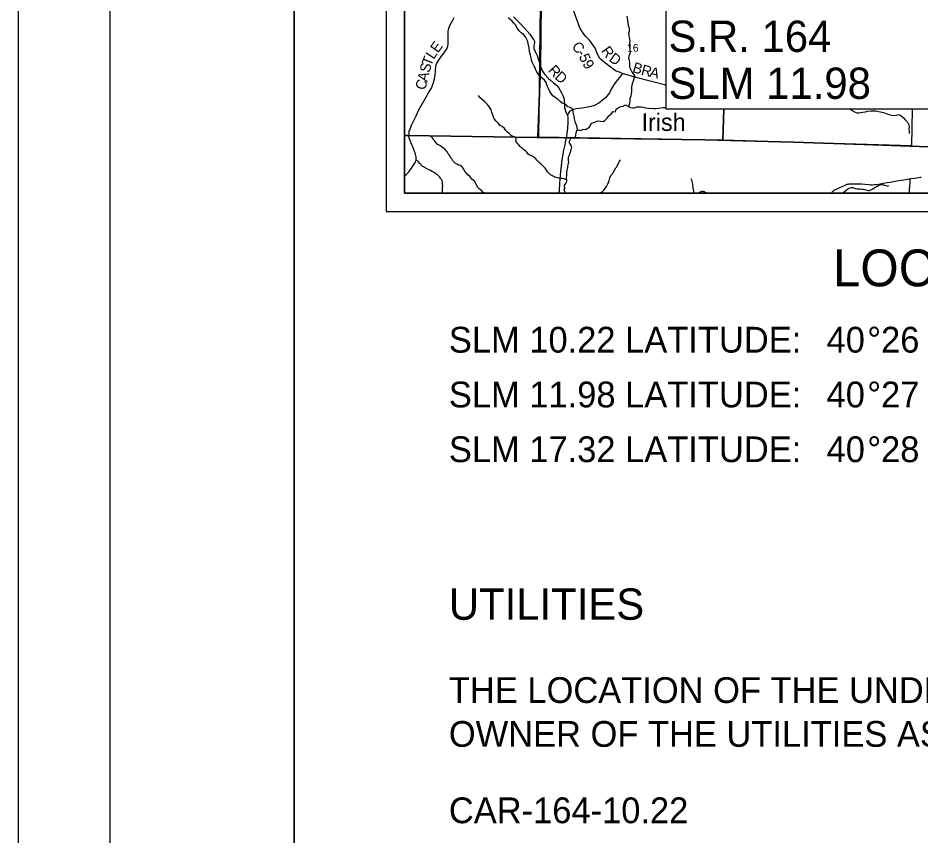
# Model space of a CAD drawing. Extents: x -20.5 to 34, y -66 to 23.9.
# Drawn here: x 0 to 4.905, y 10.61 to 15.05 of the extents above; entities that cross this region are included whole.
import ezdxf

# ---------------------------------------------------------------- set-up
doc = ezdxf.new("R2010")
doc.units = 0
for name, color, linetype in [('Default', 7, 'Continuous'), ('GM_X_County_Road_Text', 7, 'Continuous'), ('GM_X_County_Text', 7, 'Continuous'), ('GM_X_Minor_Lake', 7, 'Continuous'), ('GM_X_Minor_River_Text', 7, 'Continuous'), ('GM_X_Section_Text', 7, 'Continuous'), ('GM_X_State_Route', 7, 'Continuous'), ('GM_X_Township_Road_Text', 7, 'Continuous'), ('GM_X_Township_Text', 7, 'Continuous'), ('SH_Border', 7, 'Continuous'), ('SH_Cut_Line', 7, 'Continuous'), ('SH_Data', 7, 'Continuous'), ('SH_Text', 7, 'Continuous')]:
    doc.layers.add(name, color=color, linetype=linetype)

msp = doc.modelspace()

# ---------------------------------------------------------------- linework, layer by layer
at = {"layer": 'Default'}
for points in [[(2.1, 20.9), (8.9, 20.9), (8.9, 14.1), (2.1, 14.1)], [(2.1, 14.4131), (2.1, 14.1), (7.0561, 14.1), (7.0584, 14.2237), (7.0621, 14.3264), (6.9781, 14.3273), (6.3081, 14.3344), (6.1363, 14.3365), (5.5684, 14.3427), (5.292, 14.3455), (5.219, 14.3463), (4.9964, 14.3486), (4.5952, 14.364), (4.213, 14.3756), (3.7322, 14.3888), (2.969, 14.3992), (2.823, 14.4012), (2.8202, 14.4012), (2.1154, 14.4129)]]:
    msp.add_lwpolyline(points, close=True, dxfattribs=at)
for points in [[(2.88, 18.0245), (2.8801, 18.0269), (2.8826, 18.5075), (2.8861, 18.9025), (2.8866, 19.0123), (2.1138, 19.0238), (2.1, 19.024), (2.1, 14.4131), (2.1154, 14.4129), (2.8202, 14.4012), (2.823, 14.4012), (2.8374, 14.7884), (2.8447, 15.4785), (2.8665, 16.4374), (2.8739, 17.2409)], [(2.8447, 15.4785), (2.8374, 14.7884), (2.823, 14.4012), (2.969, 14.3992), (3.7322, 14.3888), (4.213, 14.3756), (4.5952, 14.364), (4.9964, 14.3486), (5.219, 14.3463), (5.292, 14.3455), (5.5684, 14.3427), (6.1363, 14.3365), (6.3081, 14.3344), (6.9781, 14.3273), (7.0621, 14.3264), (7.1219, 14.3257), (7.8132, 14.3208), (8.0565, 14.3169), (8.0585, 14.4588), (8.0589, 14.5033), (8.0605, 14.6038), (8.0662, 14.9881), (8.0784, 15.8902)]]:
    msp.add_lwpolyline(points, dxfattribs=at)
at = {"layer": 'GM_X_County_Text'}
for points in [[(2.6908, 15.0567), (2.7066, 15.0429), (2.7294, 15.0198), (2.752, 14.9952), (2.7804, 14.962), (2.7942, 14.9419), (2.8012, 14.9328), (2.8052, 14.9254), (2.8061, 14.9174), (2.8045, 14.9069), (2.802, 14.8968), (2.8022, 14.8851), (2.8083, 14.8696), (2.8197, 14.8462), (2.8257, 14.8294), (2.8314, 14.8119), (2.8347, 14.7983)], [(2.8347, 14.7983), (2.8354, 14.7954), (2.8376, 14.7878), (2.8485, 14.7625), (2.86, 14.7456), (2.8812, 14.7225), (2.892, 14.7128), (2.9084, 14.6989), (2.9251, 14.6855), (2.9359, 14.6724), (2.9499, 14.6479), (2.9614, 14.6253), (2.9663, 14.6092), (2.9676, 14.5727), (2.9691, 14.5622), (2.972, 14.5522), (2.9765, 14.5405), (2.98, 14.5326), (2.9851, 14.5205)], [(2.3064, 14.1), (2.3063, 14.1063), (2.3063, 14.1124), (2.3066, 14.1339), (2.3067, 14.1398), (2.3066, 14.1481), (2.3064, 14.1532), (2.3059, 14.1574), (2.3052, 14.1612), (2.3045, 14.1641), (2.3037, 14.1668), (2.3027, 14.1694), (2.3014, 14.1721), (2.2993, 14.1758), (2.2971, 14.1791), (2.2951, 14.1818), (2.2904, 14.187), (2.2869, 14.1904), (2.2797, 14.1967), (2.2741, 14.2012), (2.2671, 14.2067), (2.2619, 14.2106), (2.2574, 14.2135), (2.2504, 14.2177), (2.2398, 14.223), (2.2281, 14.2286), (2.2158, 14.2348), (2.2078, 14.239), (2.2023, 14.242), (2.198, 14.245), (2.1955, 14.2468), (2.1928, 14.2491), (2.1901, 14.2516), (2.1874, 14.2543), (2.1819, 14.2607), (2.1739, 14.2709), (2.1719, 14.2731), (2.1693, 14.2755), (2.1669, 14.2772), (2.1645, 14.2786), (2.1624, 14.2797)], [(4.4182, 14.1), (4.4191, 14.1011), (4.4225, 14.1052), (4.4248, 14.1079), (4.4273, 14.1103), (4.4302, 14.1128), (4.4336, 14.1155), (4.4366, 14.1174), (4.4393, 14.119), (4.4456, 14.122), (4.4601, 14.1286), (4.4836, 14.1396), (4.4924, 14.1438), (4.4966, 14.1455), (4.5028, 14.1477), (4.509, 14.1492), (4.5143, 14.1501), (4.5199, 14.1507), (4.5249, 14.1508), (4.5343, 14.1507), (4.5558, 14.1506), (4.5634, 14.1505), (4.5718, 14.1502), (4.5786, 14.1499), (4.5841, 14.1496), (4.6, 14.1481), (4.6229, 14.1459), (4.6315, 14.1454), (4.6415, 14.1456), (4.6525, 14.146), (4.664, 14.1469), (4.6742, 14.1481), (4.7013, 14.153), (4.7214, 14.1571), (4.737, 14.16), (4.7555, 14.1635), (4.7739, 14.1664), (4.797, 14.1696), (4.812, 14.1719), (4.8208, 14.1735), (4.831, 14.1753), (4.8416, 14.1772), (4.8471, 14.1782), (4.8517, 14.179), (4.8673, 14.1813), (4.883, 14.1833), (4.8916, 14.1845), (4.8998, 14.1859), (4.906, 14.1867)], [(4.8419, 14.1), (4.8427, 14.1188), (4.8434, 14.1267), (4.8439, 14.132), (4.8449, 14.1428), (4.8458, 14.153), (4.8467, 14.1695), (4.8471, 14.1782)], [(3.7009, 14.1), (3.7012, 14.1007), (3.7022, 14.1029), (3.7033, 14.1044), (3.7052, 14.1061), (3.7077, 14.1076), (3.7104, 14.1087), (3.7125, 14.1094), (3.7145, 14.1098), (3.717, 14.1099), (3.7193, 14.1097), (3.7234, 14.1088), (3.7265, 14.1079), (3.7296, 14.1066), (3.7397, 14.1021), (3.7452, 14.1)]]:
    msp.add_lwpolyline(points, dxfattribs=at)
at = {"layer": 'GM_X_Minor_Lake'}
for points in [[(3.8345, 14.5564), (3.829, 14.3877), (2.8293, 14.4033), (2.8417, 15.4083), (3.8622, 15.401), (3.8602, 15.34)], [(4.8577, 14.5564), (4.8536, 14.3565), (3.829, 14.3877), (3.8345, 14.5564)]]:
    msp.add_lwpolyline(points, dxfattribs=at)
at = {"layer": 'GM_X_Minor_River_Text'}
for points in [[(3.3171, 14.5698), (3.3235, 14.5862), (3.3244, 14.6014), (3.3261, 14.6147), (3.33, 14.628), (3.3317, 14.6387), (3.3338, 14.6512), (3.3339, 14.6649), (3.3341, 14.6744), (3.3366, 14.687), (3.3402, 14.6995), (3.343, 14.7095), (3.3462, 14.7205), (3.3505, 14.7358), (3.3454, 14.7463), (3.3358, 14.7564), (3.3315, 14.7677), (3.3225, 14.7812), (3.3227, 14.793), (3.3232, 14.8074), (3.3207, 14.8214), (3.3183, 14.8312), (3.3199, 14.8453), (3.3258, 14.8575), (3.3264, 14.867), (3.3251, 14.8788), (3.3226, 14.8928), (3.3224, 14.9038), (3.323, 14.9148), (3.325, 14.927), (3.3213, 14.9444), (3.3189, 14.9557), (3.3183, 14.9675), (3.3215, 14.9789), (3.3217, 14.9933), (3.3169, 15.0084), (3.3136, 15.0243), (3.3122, 15.0364), (3.3105, 15.0489), (3.3092, 15.0614)], [(3.0393, 14.4413), (3.0376, 14.4573), (3.034, 14.4679), (3.0285, 14.481), (3.0225, 14.5037), (3.0207, 14.5185), (3.0182, 14.5321), (3.0154, 14.5438), (3.0094, 14.5585), (2.9964, 14.5659), (2.9866, 14.5691), (2.9773, 14.5788), (2.9662, 14.5843), (2.9567, 14.5883), (2.9448, 14.598), (2.9329, 14.6099), (2.918, 14.6184), (2.9049, 14.6281), (2.8953, 14.6408), (2.8887, 14.6517), (2.8812, 14.6671), (2.8761, 14.678), (2.8718, 14.6882), (2.8682, 14.7007), (2.8604, 14.7138), (2.8473, 14.7246), (2.8362, 14.7332), (2.8277, 14.744), (2.8199, 14.7549), (2.8125, 14.7677), (2.8085, 14.7794), (2.8038, 14.7891), (2.7984, 14.7993), (2.7933, 14.8113), (2.79, 14.8219), (2.7872, 14.834), (2.7832, 14.8487), (2.7807, 14.8608), (2.779, 14.8707), (2.7757, 14.8854), (2.774, 14.8972), (2.7719, 14.9096), (2.7691, 14.9233), (2.7616, 14.9372), (2.7569, 14.9481), (2.745, 14.9612), (2.7327, 14.9693), (2.7223, 14.9809), (2.713, 14.9933), (2.7028, 15.0136), (2.6925, 15.0225), (2.6836, 15.0334), (2.672, 15.0442), (2.6617, 15.0523)], [(2.7008, 14.403), (2.6891, 14.4074), (2.6796, 14.4126), (2.6696, 14.4215), (2.6588, 14.4301), (2.6492, 14.4405), (2.6418, 14.4503), (2.6295, 14.4618), (2.6196, 14.4677), (2.608, 14.4797), (2.5976, 14.4905), (2.5872, 14.5036), (2.5805, 14.5171), (2.5766, 14.5277), (2.5738, 14.5379), (2.5701, 14.5515), (2.5647, 14.5613), (2.5581, 14.5718), (2.5476, 14.5834), (2.5353, 14.5953), (2.523, 14.6057), (2.5096, 14.6176), (2.5018, 14.63)], [(3.0034, 14.3985), (3.0064, 14.4033), (3.0183, 14.3981), (3.0276, 14.4036), (3.0307, 14.417), (3.0325, 14.4272), (3.0349, 14.4406), (3.047, 14.4427), (3.0568, 14.4402), (3.07, 14.4468), (3.0817, 14.4455), (3.0915, 14.4502), (3.102, 14.4553), (3.1075, 14.4657), (3.1141, 14.4779), (3.1269, 14.4831), (3.1367, 14.4867), (3.1502, 14.4918), (3.1642, 14.4909), (3.1779, 14.4885), (3.188, 14.494), (3.2003, 14.5075), (3.2088, 14.5201), (3.2222, 14.531), (3.233, 14.5422), (3.2459, 14.542), (3.2494, 14.5561), (3.2592, 14.5627), (3.2738, 14.5698), (3.2867, 14.5711), (3.2987, 14.5786), (3.3124, 14.572), (3.3269, 14.5654), (3.3394, 14.5622), (3.3496, 14.5635), (3.3639, 14.5679), (3.3753, 14.5688), (3.3855, 14.5683), (3.395, 14.5673), (3.4087, 14.5633), (3.4239, 14.5606), (3.4337, 14.56), (3.4435, 14.5617), (3.4534, 14.5599), (3.4659, 14.5586), (3.4795, 14.5604), (3.4912, 14.5625), (3.504, 14.5638), (3.5146, 14.5648), (3.5212, 14.5623)], [(4.5224, 14.5564), (4.5319, 14.5486), (4.5472, 14.5394), (4.5579, 14.5366), (4.5681, 14.5364), (4.5779, 14.5377), (4.59, 14.539), (4.604, 14.5408), (4.6145, 14.544), (4.6319, 14.5462), (4.6474, 14.5468), (4.6599, 14.547), (4.6743, 14.5431), (4.685, 14.5414), (4.707, 14.5361), (4.7165, 14.5324), (4.7268, 14.5281), (4.7363, 14.5252), (4.7462, 14.5235), (4.7576, 14.5221), (4.7712, 14.5239), (4.7848, 14.526), (4.7951, 14.5213), (4.8085, 14.5105), (4.8209, 14.4955), (4.8313, 14.4843), (4.8387, 14.47), (4.8411, 14.4602), (4.8398, 14.4473), (4.84, 14.4359), (4.8402, 14.423)], [(2.5327, 14.1), (2.5326, 14.1), (2.5243, 14.1046), (2.5182, 14.1137), (2.5122, 14.1179), (2.5039, 14.1244), (2.4967, 14.1321), (2.4933, 14.1393), (2.4888, 14.1458), (2.4862, 14.1523), (2.479, 14.1645), (2.4718, 14.1706), (2.4643, 14.1759), (2.4594, 14.182), (2.4537, 14.1904), (2.4435, 14.1996), (2.4329, 14.2118), (2.4273, 14.2187), (2.4239, 14.2259), (2.4167, 14.2377), (2.4107, 14.2438), (2.402, 14.25), (2.3933, 14.2515), (2.3846, 14.2569), (2.377, 14.2615), (2.371, 14.2664), (2.3627, 14.2756), (2.3559, 14.2855), (2.3499, 14.2928), (2.3468, 14.3), (2.3416, 14.308), (2.3374, 14.3137), (2.3322, 14.3229), (2.3257, 14.3298), (2.3197, 14.3366), (2.3118, 14.3443), (2.3046, 14.3496), (2.2989, 14.3534), (2.2914, 14.3584), (2.277, 14.3657), (2.2706, 14.3726), (2.2638, 14.3813), (2.2555, 14.3901), (2.2513, 14.3993), (2.2419, 14.4104)], [(2.9791, 14.1723), (2.9655, 14.1774), (2.9579, 14.1785), (2.9511, 14.1793), (2.9435, 14.1805), (2.9378, 14.1813), (2.9302, 14.1832), (2.9223, 14.1851), (2.9166, 14.1871), (2.9105, 14.1897), (2.9033, 14.194), (2.8931, 14.1989), (2.8867, 14.2043), (2.881, 14.21), (2.8757, 14.2157), (2.8712, 14.2245), (2.8633, 14.2356), (2.8546, 14.2451), (2.8471, 14.2524), (2.8403, 14.2589), (2.8312, 14.2669), (2.8233, 14.2741), (2.8176, 14.2787), (2.8123, 14.2852), (2.8044, 14.2928), (2.7987, 14.2971), (2.7923, 14.3009), (2.7836, 14.304), (2.7771, 14.3078), (2.7696, 14.3135), (2.7636, 14.3215), (2.756, 14.3292), (2.7484, 14.3341), (2.7413, 14.3399), (2.7333, 14.3479), (2.7277, 14.3529), (2.7205, 14.3616), (2.7152, 14.3681), (2.7103, 14.3742), (2.7047, 14.3845), (2.7059, 14.3903), (2.705, 14.3969), (2.7008, 14.403)], [(3.0034, 14.3985), (2.993, 14.3807), (2.9937, 14.375), (2.9956, 14.3693), (2.9997, 14.3636), (3.0046, 14.3556), (3.0057, 14.3483), (3.0046, 14.34), (3.0019, 14.3328), (3.0007, 14.3263), (2.9988, 14.3202), (2.9965, 14.3126), (2.9934, 14.3054), (2.9915, 14.2997), (2.9888, 14.2933), (2.9876, 14.2872), (2.9883, 14.2765), (2.9894, 14.2693), (2.9886, 14.2602), (2.9871, 14.2526), (2.9852, 14.2469), (2.984, 14.2396), (2.9821, 14.2324), (2.9809, 14.2248), (2.9789, 14.2146), (2.9789, 14.2073), (2.9792, 14.1975), (2.9788, 14.191), (2.978, 14.1845), (2.978, 14.1788), (2.9791, 14.172), (2.9795, 14.1659), (2.9791, 14.1602), (2.9764, 14.153), (2.9691, 14.145), (2.9649, 14.1382), (2.9679, 14.1325), (2.969, 14.1256), (2.9656, 14.1196), (2.9659, 14.1131), (2.9701, 14.107), (2.9727, 14.1013), (2.9724, 14.1)], [(3.1637, 14.1), (3.1666, 14.1028), (3.1742, 14.1092), (3.1815, 14.116), (3.1891, 14.1267), (3.1963, 14.1354), (3.2009, 14.1426), (3.2044, 14.1506), (3.2086, 14.1593), (3.2109, 14.1688), (3.2128, 14.1764), (3.2152, 14.1836), (3.2209, 14.1957), (3.2285, 14.2045), (3.232, 14.2121), (3.2404, 14.2253), (3.2477, 14.2367), (3.2538, 14.2447), (3.2568, 14.2515), (3.2595, 14.2576), (3.2637, 14.2648), (3.2679, 14.2724), (3.2729, 14.2803)], [(3.6553, 14.1785), (3.6586, 14.1712), (3.6601, 14.1644), (3.6612, 14.1579), (3.6631, 14.1473), (3.6642, 14.1415), (3.6649, 14.1347), (3.666, 14.1267), (3.6679, 14.1206), (3.6686, 14.1145), (3.6693, 14.1088), (3.6701, 14.1012), (3.6701, 14.1)], [(4.4773, 14.1), (4.4798, 14.1012), (4.5003, 14.1179), (4.5072, 14.1224), (4.5182, 14.1277), (4.5251, 14.1299), (4.5349, 14.1299), (4.547, 14.1257), (4.5588, 14.1233), (4.5679, 14.1226), (4.5751, 14.1225), (4.5838, 14.1217), (4.5903, 14.1209), (4.5986, 14.1198), (4.6058, 14.1175), (4.6119, 14.1155), (4.6176, 14.114), (4.6252, 14.1144), (4.6331, 14.117), (4.6407, 14.1219), (4.648, 14.1264), (4.6544, 14.1306), (4.6643, 14.1366), (4.6742, 14.1412), (4.6837, 14.1442), (4.6906, 14.1457), (4.6966, 14.1464), (4.7061, 14.1437), (4.7137, 14.1414), (4.7205, 14.1402), (4.7262, 14.1402), (4.731, 14.1411)]]:
    msp.add_lwpolyline(points, dxfattribs=at)
at = {"layer": 'GM_X_State_Route'}
for points in [[(3.2831, 14.7492), (3.2678, 14.7556), (3.2458, 14.7638), (3.216, 14.785), (3.1863, 14.8091), (3.1608, 14.8315), (3.1475, 14.8544), (3.135, 14.8863), (3.1138, 14.9171), (3.1026, 14.9314), (3.0851, 14.9506), (3.0694, 14.9687), (3.0509, 14.9976), (3.0183, 15.0873)], [(2.3677, 15.0513), (2.3594, 15.0371), (2.3452, 15.0112), (2.3415, 15.0025), (2.338, 14.9927), (2.3348, 14.9788), (2.3342, 14.9655), (2.3352, 14.9567), (2.3352, 14.9379), (2.3342, 14.911), (2.3323, 14.8959), (2.3289, 14.8858), (2.3126, 14.8623), (2.2989, 14.8439), (2.2859, 14.8251), (2.2747, 14.8071), (2.2697, 14.7954), (2.2673, 14.7858), (2.2657, 14.7634), (2.2641, 14.7421), (2.2601, 14.7181), (2.2554, 14.6978), (2.2451, 14.6736), (2.2319, 14.6501), (2.2189, 14.6255), (2.1762, 14.5503), (2.1612, 14.5184), (2.1364, 14.4671), (2.1275, 14.4453), (2.1232, 14.4355), (2.122, 14.4093)], [(3.5212, 14.6838), (3.5211, 14.6838), (3.511, 14.6884), (3.3564, 14.7267), (3.2831, 14.7492), (3.265, 14.7266), (3.2442, 14.6989), (3.2242, 14.667), (3.2125, 14.644), (3.1909, 14.6166), (3.1557, 14.5889), (3.1314, 14.5753), (3.1049, 14.5678), (3.0651, 14.5613), (3.0322, 14.5583), (3.0171, 14.5546), (2.9983, 14.5444), (2.9907, 14.5356), (2.9851, 14.5205), (2.986, 14.5101), (2.9869, 14.4856), (2.984, 14.4506), (2.978, 14.3975)], [(2.1, 14.1934), (2.1069, 14.1997), (2.1128, 14.2054), (2.1167, 14.2097), (2.1221, 14.2159), (2.1282, 14.2234), (2.1329, 14.2298), (2.1375, 14.2359), (2.1436, 14.2443), (2.1521, 14.2567), (2.1559, 14.2628), (2.1581, 14.2669), (2.1599, 14.2711), (2.1613, 14.2752), (2.162, 14.278), (2.1624, 14.2797), (2.1629, 14.2826), (2.1633, 14.2857), (2.1635, 14.2881), (2.1632, 14.2945), (2.1625, 14.2987), (2.1616, 14.3026), (2.1597, 14.309), (2.1564, 14.3187), (2.1537, 14.3264), (2.1437, 14.3517), (2.1399, 14.3614), (2.1267, 14.3947), (2.1245, 14.4004), (2.1228, 14.4059), (2.122, 14.4093)], [(2.94, 14.1), (2.941, 14.1115), (2.944, 14.1542), (2.9487, 14.2186), (2.9505, 14.235), (2.9515, 14.2446), (2.9548, 14.2687), (2.9615, 14.3128), (2.965, 14.3331), (2.9695, 14.3547), (2.9755, 14.3836), (2.9767, 14.3902), (2.978, 14.3975)]]:
    msp.add_lwpolyline(points, dxfattribs=at)
at = {"layer": 'SH_Border'}
for points in [[(0.5, 21.5), (1.5, 21.5), (1.5, 0.5), (0.5, 0.5)], [(1.5, 21.5), (33.5, 21.5), (33.5, 0.5), (1.5, 0.5)]]:
    msp.add_lwpolyline(points, close=True, dxfattribs=at)
at = {"layer": 'SH_Cut_Line'}
for points in [[(0, 0), (34, 0), (34, 22), (0, 22)], [(2.1, 14.4131), (2.1, 14.1), (8.9, 14.1), (8.9, 14.3068), (8.8167, 14.3089), (8.0565, 14.3169), (7.8132, 14.3208), (7.1219, 14.3257), (7.0621, 14.3264), (6.9781, 14.3273), (6.3081, 14.3344), (6.1363, 14.3365), (5.5684, 14.3427), (5.292, 14.3455), (5.219, 14.3463), (4.9964, 14.3486), (4.5952, 14.364), (4.213, 14.3756), (3.7322, 14.3888), (2.969, 14.3992), (2.823, 14.4012), (2.8202, 14.4012), (2.1154, 14.4129)]]:
    msp.add_lwpolyline(points, close=True, dxfattribs=at)
msp.add_lwpolyline([(2.1, 20.9), (2.1, 14.4131), (2.1154, 14.4129), (2.8202, 14.4012), (2.823, 14.4012), (2.969, 14.3992), (3.7322, 14.3888), (4.213, 14.3756), (4.5952, 14.364), (4.9964, 14.3486)], dxfattribs=at)
at = {"layer": 'SH_Data'}
for p, q in [((2, 21), (2, 14)), ((2.1, 20.9), (2.1, 14.1)), ((2.1, 14.1), (8.9, 14.1)), ((2.1, 14.1), (2.1, 14.1)), ((2, 14), (9, 14))]:
    msp.add_line(p, q, dxfattribs=at)
at = {"layer": 'SH_Text'}
msp.add_lwpolyline([(3.5212, 15.34), (5.6922, 15.34), (5.6922, 14.5564), (3.5212, 14.5564)], close=True, dxfattribs=at)

# ---------------------------------------------------------------- texts
at = {"layer": 'GM_X_County_Road_Text'}
msp.add_text('Irish', height=0.0947, rotation=359.9605, dxfattribs=at).set_placement((3.3871, 14.4375))
at = {"layer": 'GM_X_Section_Text'}
for s, rotation, p in [('R', 313.0167, (2.8759, 14.7631)), ('D', 318.2306, (2.9117, 14.7251))]:
    msp.add_text(s, height=0.0568, rotation=rotation, dxfattribs=at).set_placement(p)
at = {"layer": 'GM_X_Township_Road_Text'}
for s, rotation, p in [('E', 54.6551, (2.2811, 14.8571)), ('C', 310.2546, (3.0045, 14.8935)), ('L', 56.1138, (2.2576, 14.8222)), ('-', 304.0321, (3.0337, 14.8591)), ('R', 305.9726, (3.1654, 14.8719)), ('D', 323.3497, (3.2057, 14.821)), ('T', 69.2714, (2.2442, 14.7855)), ('5', 293.311, (3.0454, 14.8423)), ('9', 302.5732, (3.0639, 14.8013)), ('S', 75.6088, (2.2351, 14.7499)), ('B', 343.3976, (3.334, 14.7577)), ('R', 345.8477, (3.3813, 14.7436)), ('A', 346.027, (3.4267, 14.7322)), ('C', 75.8123, (2.2115, 14.6563)), ('A', 75.8052, (2.2229, 14.7015))]:
    msp.add_text(s, height=0.0568, rotation=rotation, dxfattribs=at).set_placement(p)
at = {"layer": 'GM_X_Township_Text'}
msp.add_text('16', height=0.04186, rotation=0, dxfattribs=at).set_placement((3.3086, 14.8675))
at = {"layer": 'SH_Text'}
for s, height, p in [('S.R. 164', 0.17, (3.5335, 14.8664)), ('SLM 11.98', 0.17, (3.5335, 14.6114)), ('LOCATION MAP', 0.2, (4.4269, 13.5937)), ('SLM 10.22 LATITUDE:  ', 0.14, (2.3403, 13.2338)), (' 40', 0.14, (4.3402, 13.2338)), ('°', 0.14, (4.6135, 13.2338)), ('26', 0.14, (4.6883, 13.2338)), ('SLM 11.98 LATITUDE:  ', 0.14, (2.3403, 12.9364)), (' 40', 0.14, (4.3402, 12.9364)), ('°', 0.14, (4.6135, 12.9364)), ('27', 0.14, (4.6883, 12.9364)), ('SLM 17.32 LATITUDE:  ', 0.14, (2.3403, 12.6391)), (' 40', 0.14, (4.3402, 12.6391)), ('°', 0.14, (4.6135, 12.6391)), ('28', 0.14, (4.6883, 12.6391)), ('UTILITIES', 0.17, (2.3403, 11.7833)), ('THE LOCATION OF THE UNDERGROUND UTILITIES SHOWN ON THE PLANS ARE OBTAINED FROM THE', 0.14, (2.3403, 11.3315)), ('OWNER OF THE UTILITIES AS REQUIRED BY SECTION 153.64 O.R.C.', 0.14, (2.3403, 11.0935)), ('CAR-164-10.22', 0.14, (2.3403, 10.6787))]:
    msp.add_text(s, height=height, dxfattribs=at).set_placement(p)

doc.saveas('drawing.dxf')
